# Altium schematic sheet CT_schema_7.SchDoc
size 287 x 160 mm
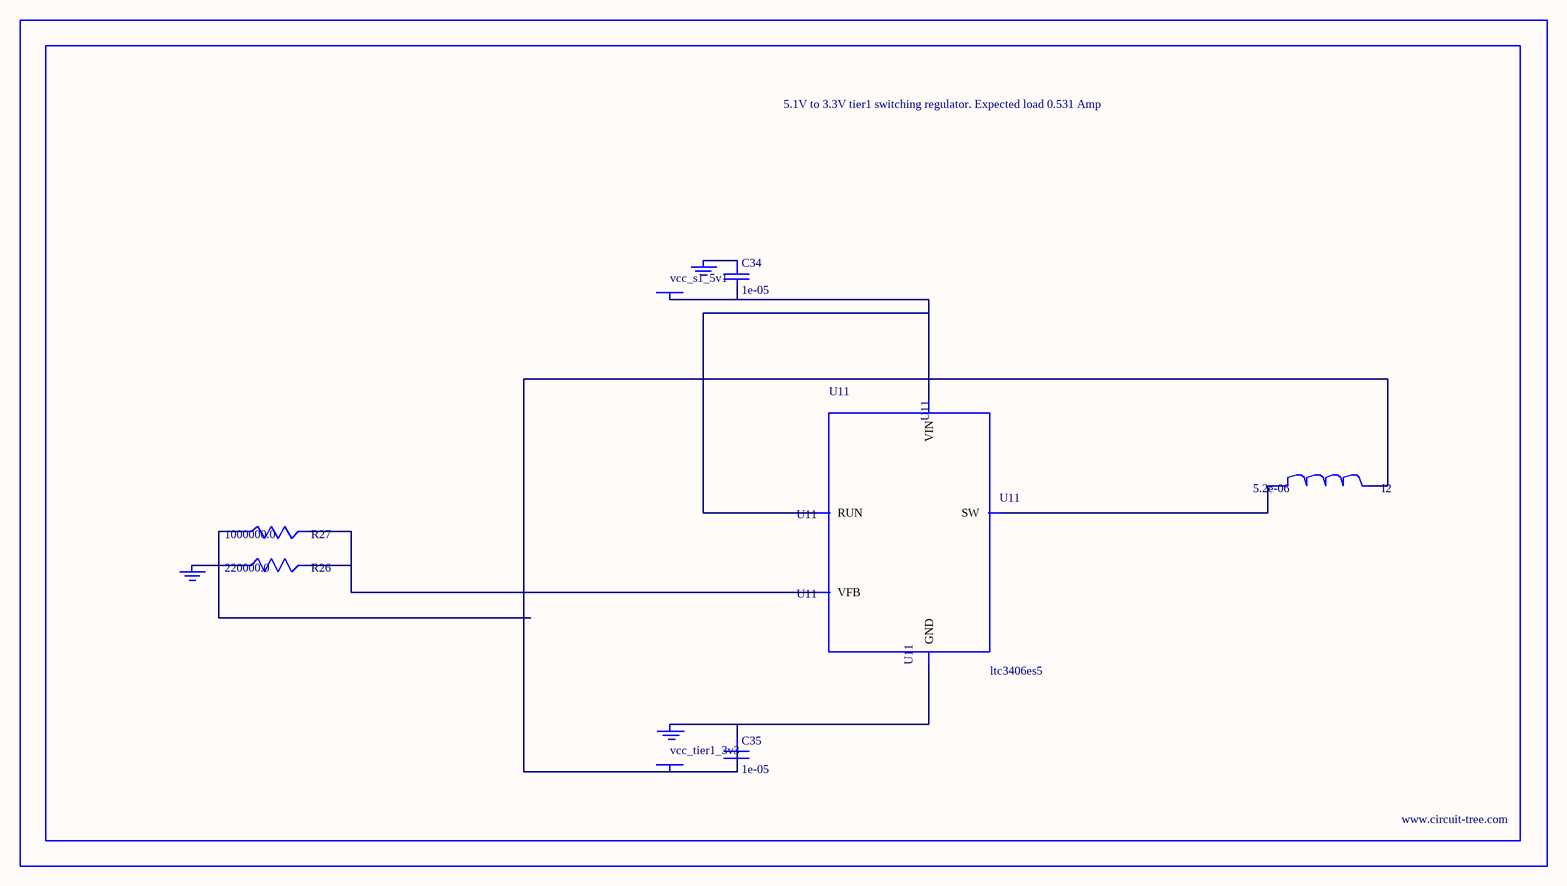
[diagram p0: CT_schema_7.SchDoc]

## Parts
BORDER6  (no value)
C34  1e-05  [C0805]
C35  1e-05  [C0805]
GND_INSTANCE_6_0  (no value)
GND_INSTANCE_6_1  (no value)
GND_INSTANCE_6_2  (no value)
I2  5.2e-06  [DR1040]
POWER_INSTANCE_6_0  vcc_tier1_3v3
POWER_INSTANCE_6_1  vcc_s1_5v1
R26  220000.0  [R0603]
R27  1000000.0  [R0603]
U11  ltc3406es5  [TSOT-23-5]

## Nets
NetC34_1: C34.1 GND_INSTANCE_6_1.0(GND)
NetC34_2: C34.2 POWER_INSTANCE_6_1.0(PWR) U11.1(RUN) U11.4(VIN)
NetC35_1: C35.1 GND_INSTANCE_6_0.0(GND) U11.2(GND)
NetC35_2: C35.2 I2.2 POWER_INSTANCE_6_0.0(PWR) R27.1
NetGND_INSTANCE_6_2_0: GND_INSTANCE_6_2.0(GND) R26.1
NetI2_1: I2.1 U11.3(SW)
NetR26_2: R26.2 R27.2 U11.5(VFB)

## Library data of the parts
BORDER6 = BORDER_PAGE6
C34 C35 = C0805C106K8RACTU
GND_INSTANCE_6_0-GND_INSTANCE_6_2 = GND
I2 = DR1040-5R2-R
POWER_INSTANCE_6_0 POWER_INSTANCE_6_1 = PWR
R26 = RC0603JR-07220KL
R27 = RC0603JR-071ML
